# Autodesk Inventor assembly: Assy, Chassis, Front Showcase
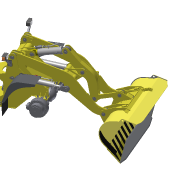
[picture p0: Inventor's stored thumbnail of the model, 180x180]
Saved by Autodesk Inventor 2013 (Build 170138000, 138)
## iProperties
Created: 2005-04
Part Number: Assy, Chassis, Front Showcase
Document SubType Name: Assembly
Designer: salex
Manufacturer: Standard
Standards Organization: Custom
Author: salex
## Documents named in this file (11)
- C:\Product Design Suite 2013 Test Drive\Inventor to Showcase\Workspace\Assy, Chassis, Front Showcase, Layout.iam
- C:\Product Design Suite 2013 Test Drive\Inventor to Showcase\Workspace\Assy, Chassis, Front\PK46.25.03.000.iam
- C:\Product Design Suite 2013 Test Drive\Inventor to Showcase\Workspace\Assy, Chassis, Front\_bucket PK46.80.00.000.iam
- C:\Product Design Suite 2013 Test Drive\Inventor to Showcase\Workspace\Assy, Chassis, Front\_boom PK46.25.01.000.iam
- C:\Product Design Suite 2013 Test Drive\Inventor to Showcase\Workspace\Assy, Chassis, Front\_PK46.21.01.100.iam
- C:\Product Design Suite 2013 Test Drive\Inventor to Showcase\Workspace\Parts\MB Hub.ipt
- C:\Product Design Suite 2013 Test Drive\Inventor to Showcase\Workspace\Assy, Chassis, Front\PK46.43.04.020.iam
- C:\Product Design Suite 2013 Test Drive\Inventor to Showcase\Workspace\Assy, Chassis, Front\PK46.43.02.010.iam
- C:\Product Design Suite 2013 Test Drive\Inventor to Showcase\Workspace\Assy, Chassis, Front\PK46.43.01.010.iam
- C:\Product Design Suite 2013 Test Drive\Inventor to Showcase\Workspace\Assy, Chassis, Front\PK46.43.03.020.iam
- C:\Product Design Suite 2013 Test Drive\Inventor to Showcase\Workspace\Assy, Chassis, Front\LayoutPK46.ipt
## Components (12 placed, 10 different names)
1. _PK46.21.01.100:1 [sub-assembly] — Mate:1, TBS, Bucket_Lift, Mate:35, Angle:3, Mate:36, Mate:39
2. PK46.25.03.000:1 [sub-assembly] — Mate:21, Mate:25, Mate:26
3. _bucket PK46.80.00.000:1 [sub-assembly] — Mate:19, Mate:20, Mate:21
4. _boom PK46.25.01.000:1 [sub-assembly] — Mate:1, TBS, Mate:19, Mate:20, Mate:23, Flush:1, Bucket_Lift, Bucket_Angle, Mate:37
5. MB Hub:1 — Mate:23, Flush:1, Mate:25, Mate:26, Bucket_Angle
6. PK46.43.04.020:1 [sub-assembly]
7. PK46.43.02.010:1 [sub-assembly]
8. PK46.43.01.010:1 [sub-assembly]
9. PK46.43.03.020:1 [sub-assembly]
10. LayoutPK46:1 — Mate:32, Mate:33, Mate:34, Angle:3
11. PK46.43.01.010:2 [sub-assembly] — Mate:37, Mate:38
12. PK46.43.03.020:2 [sub-assembly] — Mate:36, Mate:38, Mate:39
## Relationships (20: Mate 16, Angle 3, Flush 1)
- Mate:1: _PK46.21.01.100:1 ↔ _boom PK46.25.01.000:1
- TBS [Mate]: _PK46.21.01.100:1 ↔ _boom PK46.25.01.000:1
- Mate:19: _bucket PK46.80.00.000:1 ↔ _boom PK46.25.01.000:1
- Mate:20: _bucket PK46.80.00.000:1 ↔ _boom PK46.25.01.000:1
- Mate:21: PK46.25.03.000:1 ↔ _bucket PK46.80.00.000:1
- Mate:23: _boom PK46.25.01.000:1 ↔ MB Hub:1
- Flush:1: _boom PK46.25.01.000:1 ↔ MB Hub:1
- Mate:25: PK46.25.03.000:1 ↔ MB Hub:1
- Mate:26: PK46.25.03.000:1 ↔ MB Hub:1
- Bucket_Lift [Angle]: _PK46.21.01.100:1 ↔ _boom PK46.25.01.000:1
- Bucket_Angle [Angle]: _boom PK46.25.01.000:1 ↔ MB Hub:1
- Mate:32: LayoutPK46:1
- Mate:33: LayoutPK46:1
- Mate:34: LayoutPK46:1
- Mate:35: _PK46.21.01.100:1
- Angle:3: _PK46.21.01.100:1 ↔ LayoutPK46:1
- Mate:36: _PK46.21.01.100:1 ↔ PK46.43.03.020:2
- Mate:37: _boom PK46.25.01.000:1 ↔ PK46.43.01.010:2
- Mate:38: PK46.43.01.010:2 ↔ PK46.43.03.020:2
- Mate:39: _PK46.21.01.100:1 ↔ PK46.43.03.020:2
## Named parameters: Driveme = 265 deg, BucketAngle = 44 deg, d679_d4 = 0
